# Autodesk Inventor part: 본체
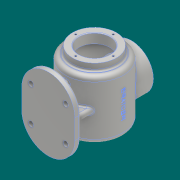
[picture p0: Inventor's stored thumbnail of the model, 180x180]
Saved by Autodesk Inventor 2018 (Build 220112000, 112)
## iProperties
Created: 2023-01
Part Number: 본체
Material: 알루미늄 6061
Document SubType Name: Modeling
Designer: 강의실01
Density: 2.7 g/cm^3
Appearance: 알루미늄 - 평지
Mass: 1033.12 g
Surface Area: 1156.75 cm^2
Volume: 382.638 cm^3
Author: 강의실01
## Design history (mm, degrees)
sketch "스케치1"
  geometry: L1 (0, 17)-(0, -17); L2 (-46, 17)-(-46, -17); L3 (46, -17)-(46, 17); C1 r 4.5 at (30, 30); C2 r 4.5 at (30, -30); C3 r 4.5 at (-30, 30); C4 r 4.5 at (-30, -30); A1 r 46 centre (0, 17) between (46, 17) and (-46, 17); A2 r 46 centre (0, -17) between (-46, -17) and (46, -17); 2 further points
  constraints: 8 end point, 6 centre point, 4 point on circle, 4 tangent, 2 coincident, 2 horizontal alignment, 2 vertical alignment, 1 midpoint, 1 parallel, 1 vertical
  dimensions: "d0" = 92 distance between parallel lines of L2 L3; "d1" = 34 distance of L1.end L1.start; "d2" = 126 dimension on A2 A1 (derived); "d3" = 9 diameter of C1; "d4" = 9 diameter of C2; "d5" = 9 diameter of C3; "d6" = 9 diameter of C4; "d7" = 30 horizontal distance of point (0, 0) C1.centre; "d8" = 30 horizontal distance of C2.centre point (0, 0); "d9" = 30 horizontal distance of C1.centre point (0, 0); "d10" = 30 horizontal distance of C3.centre point (0, 0)
extrude "돌출1" new body sketch "스케치1" distance "d11" = 10; taper "d12" = 0 deg
sketch "스케치3" dims "d0" = 92, "d1" = 34, "d2" = 126 (derived)
  geometry: L1 (80, 181)-(80, -59); L2 (0, -17)-(0, 17) reference; L3 (107, 63)-(118, 63) reference; L4 (118, 63)-(118, 51); L5 (118, 51)-(122, 51); L6 (130, 43)-(130, -42.827); L7 (107, 63)-(107, 46); L8 (125, -42.827)-(125, 43); L9 (122, 46)-(107, 46); A1 r 120 centre (80, 61) between (80, -59) and (125, -50.243); A2 r 8 centre (122, -42.827) between (125, -50.243) and (130, -42.827); A3 r 8 centre (122, 43) between (130, 43) and (122, 51); A4 r 115 centre (80, 61) between (80, -54) and (123.125, -45.608); A5 r 3 centre (122, -42.827) between (123.125, -45.608) and (125, -42.827); A6 r 3 centre (122, 43) between (125, 43) and (122, 46); 2 further points
  constraints: 16 end point, 13 point on circle, 6 centre point, 6 tangent, 4 perpendicular, 2 horizontal, 2 point on line, 1 vertical, 2 other
  dimensions: "d18" = 80 distance between parallel lines of L2 L1; "d19" = 76 diameter of L4 L1; "d20" = 100 diameter of L6 L1; "d21" = 12 distance of L3.end L4.end; "d24" = 8 radius of A2; "d25" = 8 radius of A3 (derived); "d27" = 54 diameter of L7 L1; "d33" = 120 radius of A1; "d35" = 122 distance from line of L1.end L3; "d36" = 5 distance between parallel lines of L6 L8; "d38" = 105.82678 distance from line of L6.end L3; "d39" = 118 distance from line of L1.start L3
revolve "회전1" sketch "스케치3" stored, may be unused: angle "d37" = 90 deg
sketch "스케치4"
  geometry: L1 (30, 43)-(30, -42.827) reference; L2 (10, 17)-(10, 63) reference; L3 (10, -63)-(10, -17) reference; L4 (10, 40)-(30, 34.641); L5 (10, -40)-(30, -34.641); L6 (0, 63)-(10, 63) reference; 1 further point
  constraints: 4 end point, 2 midpoint, 2 point on line
  dimensions: "d40" = 23 distance from line of L4.start L6; "d41" = 80 distance of L5.start L4.start; "d42" = 105 deg angle of L2 L4; "d43" = 105 deg angle of L3 L5
node "작업 평면1"
sketch "스케치5"
  geometry: L1 (-42, 51)-(42, 51) reference; C1 r 38 at (0, 0); 1 further point
  constraints: 1 centre point, 1 coincident
  dimensions: "d57" = 76 diameter of C1; "d58" = 51 distance from line of C1.centre L1
extrude "돌출3" join sketch "스케치5" stored distance "d59" = 70; taper "d60" = 0 deg
sketch "스케치6"
  geometry: L1 (-30, 0)-(30, 0); L2 (-30, -5)-(30, -5); L3 (30, 5)-(-30, 5); A1 r 5 centre (-30, 0) between (-30, 5) and (-30, -5); A2 r 5 centre (30, 0) between (30, -5) and (30, 5); 2 further points
  constraints: 8 end point, 4 point on circle, 4 tangent, 2 centre point, 2 coincident, 1 horizontal, 1 midpoint, 1 parallel
  dimensions: "d61" = 10 diameter of A2; "d62" = 30 distance of L1.start point (0, 0)
extrude "돌출4" join sketch "스케치6" stored distance "d63" = 70; taper "d64" = 0 deg
feature "리브3" dims "d65" = 1, "d66" = 10, "d67" = 0, "d68" = 0, "d69" = 1, "d70" = 1
feature "리브4" dims "d71" = 1, "d72" = 10, "d73" = 0, "d74" = 0, "d75" = 1, "d76" = 1
hole "구멍1" diameter "d79" = 54; stored, may be unused: countersink angle "d83" = 90 deg, drill point angle "d85" = 0 deg; dims "d77" = 10, "d78" = 10, "d80" = 6, "d81" = 4, "d82" = 2, "d84" = 50
sketch "스케치7"
  geometry: 2 further points
  constraints: 1 horizontal alignment
  dimensions: "d86" = 32.5 distance of point (0, 0) point (-32.5, 0)
hole "구멍2" sketch "스케치7" at (-32.5, 0) diameter "d87" = 3.242; stored, may be unused: countersink angle "d91" = 90 deg, drill point angle "d93" = 118 deg; dims "d88" = 8, "d89" = 4, "d90" = 2, "d92" = 10
sketch "스케치8"
  geometry: C1 r 27 at (0, 0) reference; 2 further points
  constraints: 1 vertical alignment
  dimensions: "d97" = 32.5 distance of C1.centre point (0, 32.5)
hole "구멍3" sketch "스케치8" at (0, 32.5) diameter "d98" = 3.242; stored, may be unused: countersink angle "d102" = 90 deg, drill point angle "d104" = 118 deg; dims "d99" = 8, "d100" = 4, "d101" = 2, "d103" = 10
node "작업 평면2"
sketch "스케치9"
  geometry: L1 (42, 63)-(118, 63) reference; L2 (0, 17)-(0, -17) reference; 3 further points
  constraints: 1 midpoint, 1 vertical alignment, 1 other
  dimensions: "d109" = 63 distance from line of point (80, 0) L1; "d115" = 80 distance from line of L2 point (80, 0) (derived)
feature "엠보싱1" sketch "스케치9" dims "d0" = 92, "d1" = 34, "d2" = 126 (derived), "d18" = 80, "d19" = 76, "d20" = 100, "d21" = 12, "d24" = 8, "d25" = 8 (derived), "d27" = 54, "d33" = 120, "d35" = 122, "d36" = 5, "d38" = 105.82678, "d39" = 118, "d110" = 0.5, "d111" = 0
chamfer "모따기1" distance "d112" = 1; stored, may be unused: second distance "d113" = 2, angle "d114" = 45 deg
fillet "모깎기1" dims "d116" = 3
node "솔리드1"
pattern_circular "원형 패턴1" dims angle "d95" = 360 deg
pattern_circular "원형 패턴2" dims angle "d106" = 360 deg
other parameters: "d56" = 144
